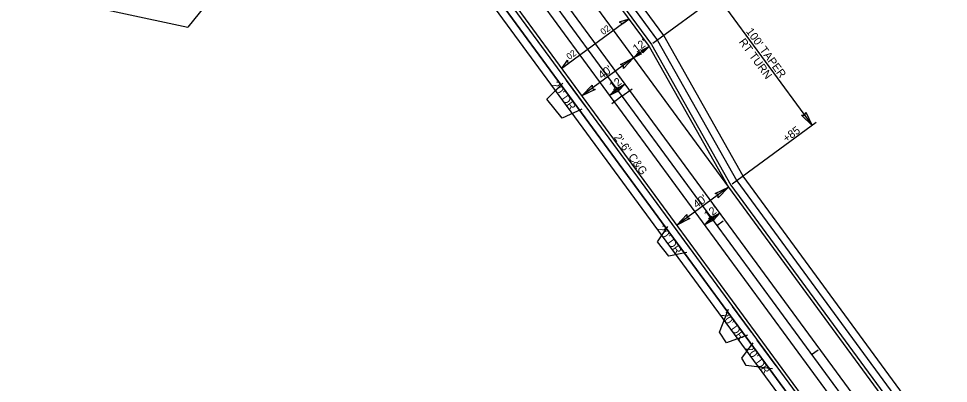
# Model space of a CAD drawing. Extents: x 1762196 to 1766326, y 709922 to 713142.
# Drawn here: x 1763131 to 1763712, y 712001 to 712229 of the extents above; entities that cross this region are included whole.
import ezdxf

# ---------------------------------------------------------------- set-up
doc = ezdxf.new("R2010")
doc.units = 0
for name, color, linetype in [('Old_Level_3', 7, 'Continuous'), ('Pattern 1', 7, 'Continuous'), ('Pattern 2', 7, 'Continuous'), ('Pattern 4', 7, 'Continuous'), ('Prop Conc 2ft 6in Curb and Gutter', 7, 'Continuous'), ('Prop Dimension', 7, 'Continuous'), ('Prop EOT', 7, 'Continuous'), ('Prop Horizontal Alignment', 7, 'Continuous'), ('Prop Horizontal Alignment Station Label', 7, 'Continuous'), ('Prop Horizontal Alignment Tick Large', 7, 'Continuous'), ('Prop Horizontal Alignment Tick Small', 7, 'Continuous'), ('Prop Lane Lines', 7, 'Continuous'), ('Prop Superelevation  Arrow CELL', 7, 'Continuous'), ('Prop Superelevation Label', 7, 'Continuous'), ('Prop Terminator CELL', 7, 'Continuous')]:
    doc.layers.add(name, color=color, linetype=linetype)

msp = doc.modelspace()

# ---------------------------------------------------------------- linework, layer by layer
at = {"layer": 'Old_Level_3'}
for p, q in [((1763461.33, 712178.51), (1763471.35, 712188.44)), ((1763471.08, 712166.63), (1763461.33, 712178.51)), ((1763483.23, 712172.3), (1763471.08, 712166.63)), ((1763530.64, 712089.56), (1763537.06, 712099.07)), ((1763537.63, 712080.68), (1763530.64, 712089.56)), ((1763548.93, 712082.93), (1763537.63, 712080.68)), ((1763569.23, 712033.12), (1763574.99, 712047.49)), ((1763573.64, 712026.61), (1763569.23, 712033.12)), ((1763586.86, 712031.34), (1763573.64, 712026.61)), ((1763583.16, 712016.95), (1763590.42, 712026.5)), ((1763585.87, 712012.44), (1763583.16, 712016.95)), ((1763602.3, 712010.35), (1763585.87, 712012.44))]:
    msp.add_line(p, q, dxfattribs=at)
at = {"layer": 'Pattern 1'}
for p, q in [((1763534.54, 712218.15), (1763397.52, 712404.5)), ((1763845.53, 711677), (1763341.12, 712363.03)), ((1763337.1, 712360.07), (1763843.84, 711670.85)), ((1763584.11, 712130.47), (1763534.54, 712218.15)), ((1763530.51, 712215.18), (1763580.08, 712127.51)), ((1763855.15, 711761.83), (1763584.11, 712130.47)), ((1763580.08, 712127.51), (1763851.12, 711758.87))]:
    msp.add_line(p, q, dxfattribs=at)
msp.add_lwpolyline([(1763397.52, 712404.5), (1763393.49, 712401.54), (1763530.51, 712215.18)], dxfattribs=at)
at = {"layer": 'Pattern 2'}
for p, q in [((1763534.54, 712218.15), (1763397.52, 712404.5)), ((1763393.49, 712401.54), (1763530.51, 712215.18)), ((1763341.12, 712363.03), (1763845.53, 711677)), ((1763337.1, 712360.07), (1763843.84, 711670.85)), ((1763584.11, 712130.47), (1763534.54, 712218.15)), ((1763530.51, 712215.18), (1763580.08, 712127.51)), ((1763855.15, 711761.83), (1763584.11, 712130.47)), ((1763580.08, 712127.51), (1763851.12, 711758.87))]:
    msp.add_line(p, q, dxfattribs=at)
at = {"layer": 'Pattern 4'}
for p, q in [((1763485.64, 712174.07), (1763473.77, 712190.22)), ((1763551.35, 712084.7), (1763539.48, 712100.85)), ((1763589.28, 712033.12), (1763577.41, 712049.26)), ((1763604.71, 712012.13), (1763592.84, 712028.27))]:
    msp.add_line(p, q, dxfattribs=at)
at = {"layer": 'Prop Conc 2ft 6in Curb and Gutter'}
for p, q in [((1763389.87, 712398.87), (1763526.88, 712212.52)), ((1763344.75, 712365.7), (1763842.1, 711689.26)), ((1763526.88, 712212.52), (1763576.45, 712124.84)), ((1763576.45, 712124.84), (1763847.5, 711756.2))]:
    msp.add_line(p, q, dxfattribs=at)
at = {"layer": 'Prop Dimension'}
for p, q in [((1763570.39, 712244.51), (1763527.69, 712213.11)), ((1763567.97, 712242.73), (1763627.21, 712162.16)), ((1763525.27, 712211.33), (1763515.6, 712204.23)), ((1763515.6, 712204.23), (1763483.38, 712180.53)), ((1763510.25, 712187.88), (1763500.58, 712180.77)), ((1763629.63, 712163.94), (1763577.26, 712125.44)), ((1763574.84, 712123.66), (1763542.61, 712099.96)), ((1763569.48, 712107.31), (1763559.82, 712100.2))]:
    msp.add_line(p, q, dxfattribs=at)
at = {"layer": 'Prop EOT'}
for p, q in [((1763388.26, 712397.69), (1763525.27, 712211.33)), ((1763346.36, 712366.89), (1763843.71, 711690.45)), ((1763525.27, 712211.33), (1763574.84, 712123.66)), ((1763574.84, 712123.66), (1763845.88, 711755.02))]:
    msp.add_line(p, q, dxfattribs=at)
at = {"layer": 'Prop Horizontal Alignment'}
msp.add_line((1763362.47, 712378.73), (1764087.96, 711392.01), dxfattribs=at)
at = {"layer": 'Prop Horizontal Alignment Station Label'}
for p in [(1763362.47, 712378.73), (1763131.45, 712246.11)]:
    msp.add_line(p, (1763237.09, 712223.4), dxfattribs=at)
at = {"layer": 'Prop Horizontal Alignment Tick Large'}
for q in [(1763514.82, 712185.03), (1763514.82, 712185.03), (1763501.93, 712175.55), (1763501.93, 712175.55)]:
    msp.add_line((1763508.38, 712180.29), q, dxfattribs=at)
at = {"layer": 'Prop Horizontal Alignment Tick Small'}
for p, q in [((1763567.61, 712099.73), (1763571.64, 712102.69)), ((1763567.61, 712099.73), (1763571.64, 712102.69)), ((1763626.85, 712019.16), (1763630.88, 712022.12)), ((1763626.85, 712019.16), (1763630.88, 712022.12))]:
    msp.add_line(p, q, dxfattribs=at)
at = {"layer": 'Prop Lane Lines'}
for p, q in [((1763378.59, 712390.58), (1763574.84, 712123.66)), ((1763367.31, 712382.29), (1763916.53, 711635.29)), ((1763357.64, 712375.18), (1763906.87, 711628.18))]:
    msp.add_line(p, q, dxfattribs=at)
at = {"layer": 'Prop Superelevation  Arrow CELL'}
for points in [[(1763512.66, 712228.48), (1763506.64, 712226.54), (1763508.94, 712225.74)], [(1763470.77, 712197.68), (1763474.42, 712202.85), (1763474.49, 712200.42)]]:
    msp.add_lwpolyline(points, close=True, dxfattribs=at)
at = {"layer": 'Prop Superelevation Label'}
msp.add_line((1763512.66, 712228.48), (1763470.77, 712197.68), dxfattribs=at)
at = {"layer": 'Prop Terminator CELL'}
for points in [[(1763520.37, 712208.89), (1763525.27, 712211.33), (1763521.47, 712207.34), (1763521.45, 712208.53)], [(1763520.51, 712206.68), (1763515.6, 712204.23), (1763519.41, 712208.22), (1763519.42, 712207.03)], [(1763507.43, 712200.14), (1763515.6, 712204.23), (1763509.26, 712197.58), (1763509.24, 712199.55)], [(1763505.35, 712185.43), (1763510.25, 712187.88), (1763506.44, 712183.89), (1763506.43, 712185.07)], [(1763491.55, 712184.61), (1763483.38, 712180.53), (1763489.72, 712187.18), (1763489.74, 712185.21)], [(1763505.48, 712183.22), (1763500.58, 712180.77), (1763504.39, 712184.76), (1763504.4, 712183.58)], [(1763623.13, 712170.33), (1763627.21, 712162.16), (1763620.56, 712168.51), (1763622.53, 712168.53)], [(1763566.67, 712119.58), (1763574.84, 712123.66), (1763568.5, 712117.01), (1763568.48, 712118.98)], [(1763550.78, 712104.05), (1763542.61, 712099.96), (1763548.96, 712106.61), (1763548.98, 712104.64)], [(1763564.58, 712104.86), (1763569.48, 712107.31), (1763565.68, 712103.32), (1763565.67, 712104.5)], [(1763564.72, 712102.65), (1763559.82, 712100.2), (1763563.62, 712104.19), (1763563.64, 712103.01)]]:
    msp.add_lwpolyline(points, close=True, dxfattribs=at)

# ---------------------------------------------------------------- texts
at = {"layer": 'Prop Dimension'}
for s, rotation, p in [("100' TAPER", 306.32502, (1763585.62, 712220.69)), ('RT TURN', 306.32502, (1763581.13, 712214.14)), ("12'", 36.32502, (1763517.45, 712207.34)), ("40'", 36.32502, (1763495.8, 712190.8)), ("20' DR", 306.07669, (1763464.05, 712187.33)), ("12'", 36.32502, (1763502.68, 712183.95)), ('+85', 36.32502, (1763611.08, 712151.28)), ('2\'-6" C&G', 306.2561, (1763503.02, 712154.62)), ("40'", 36.32502, (1763555.04, 712110.23)), ("12'", 36.32502, (1763561.92, 712103.38)), ("20' DR", 306.07669, (1763530.16, 712097.53)), ("20' DR", 306.07669, (1763569.82, 712043.76)), ("20' DR", 306.07669, (1763585.25, 712022.77))]:
    msp.add_text(s, height=5, rotation=rotation, dxfattribs=at).set_placement(p)
at = {"layer": 'Prop Superelevation Label'}
for p in [(1763496.71, 712218.34), (1763475.49, 712202.86)]:
    msp.add_text('02', height=4, rotation=36.32502, dxfattribs=at).set_placement(p)

doc.saveas('drawing.dxf')
